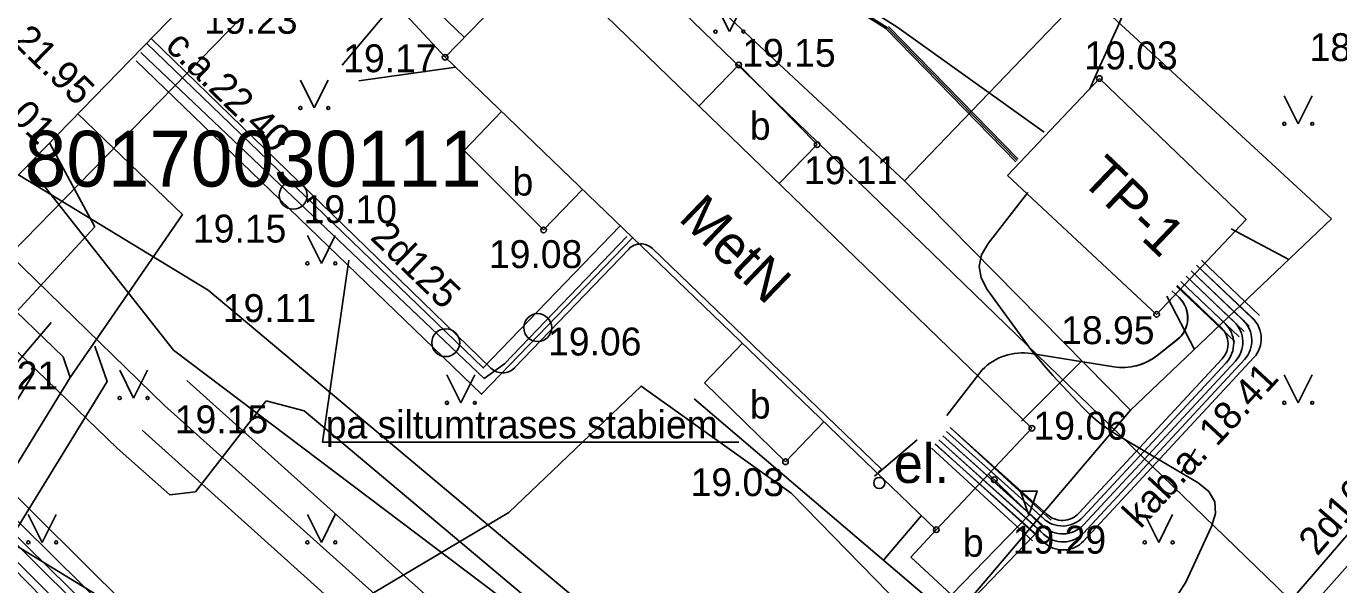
# Model space of a CAD drawing. Extents: x 532933 to 533143, y 328014 to 328163.
# Drawn here: x 533002.21 to 533025.73, y 328041.74 to 328051.75 of the extents above; entities that cross this region are included whole.
import ezdxf

# ---------------------------------------------------------------- set-up
doc = ezdxf.new("R2010")
doc.units = 0
for name, color, linetype in [('BUVE_BDET_####_####_#', 7, 'Continuous'), ('BUVE_BDET_####_TKST_#', 7, 'Continuous'), ('BUVE_EKAS_####_####_#', 7, 'Continuous'), ('BUVE_EKAS_BPAL_####_#', 7, 'Continuous'), ('BUVE_EKAS_RAKS_TKST_#', 7, 'Continuous'), ('BUVE_ELEM_####_####_#', 7, 'Continuous'), ('CELI_CMAL_####_####_#', 7, 'Continuous'), ('CKOM_ZEMJ_####_####_#', 7, 'Continuous'), ('ELEK_ACRL_####_####_#', 7, 'Continuous'), ('ELEK_ELEM_####_####_#', 7, 'Continuous'), ('ELEK_STTP_####_####_#', 7, 'Continuous'), ('ELEK_STTP_####_TKST_#', 7, 'Continuous'), ('ELEK_VADP_NEDR_####_#', 7, 'Continuous'), ('ELEK_VADP_VSPR_####_#', 7, 'Continuous'), ('ELEK_VADP_ZSPR_####_#', 7, 'Continuous'), ('ELEK_VADP_ZSPR_TKST_#', 7, 'Continuous'), ('GAZE_VADV_ASP1_####_#', 7, 'Continuous'), ('RELJ_AATZ_####_TKST_#', 7, 'Continuous'), ('RELJ_ELEM_####_####_#', 7, 'Continuous'), ('RELJ_HORZ_PAMT_####_#', 7, 'Continuous'), ('RELJ_NOGA_####_####_#', 7, 'Continuous'), ('ROBZ_UZMR_####_####_#', 7, 'Continuous'), ('ROBZ_UZMR_####_TKST_#', 7, 'Continuous'), ('SAKT_VADV_PKAB_####_#', 7, 'Continuous'), ('SILT_VADP_UDEN_####_#', 7, 'Continuous'), ('SILT_VADP_UDEN_TKAM_#', 7, 'Continuous'), ('SILT_VADP_UDEN_TKST_#', 7, 'Continuous'), ('SILT_VADV_UDEN_####_#', 7, 'Continuous'), ('SILT_VADV_UDEN_TKST_#', 7, 'Continuous'), ('TERT_ELEM_####_####_#', 7, 'Continuous')]:
    doc.layers.add(name, color=color, linetype=linetype)

msp = doc.modelspace()

# ---------------------------------------------------------------- linework, layer by layer
at = {"layer": 'BUVE_BDET_####_####_#'}
for p, q in [((533010.062, 328051.548), (533009.227, 328052.357)), ((533014.266, 328050.322), (533014.977, 328051.055)), ((533016.382, 328049.627), (533014.977, 328051.055)), ((533010.727, 328050.22), (533010.058, 328049.525)), ((533011.482, 328048.098), (533010.058, 328049.525)), ((533015.704, 328048.928), (533016.382, 328049.627)), ((533012.179, 328048.823), (533011.482, 328048.098)), ((533015.043, 328046.067), (533014.365, 328045.361)), ((533015.814, 328043.944), (533014.365, 328045.361)), ((533016.504, 328044.661), (533015.814, 328043.944)), ((533018.791, 328041.559), (533020.193, 328043.004)), ((533018.061, 328042.236), (533018.515, 328042.726))]:
    msp.add_line(p, q, dxfattribs=at)
msp.add_lwpolyline([(533019.453, 328043.722), (533020.419, 328042.785), (533019.027, 328041.34), (533018.061, 328042.236)], dxfattribs=at)
at = {"layer": 'BUVE_EKAS_####_####_#'}
msp.add_line((533000, 328046.956), (533007.034, 328054.184), dxfattribs=at)
at = {"layer": 'BUVE_EKAS_BPAL_####_#'}
for p, q in [((533009.717, 328051.192), (533018.515, 328042.726)), ((533018.515, 328042.726), (533020.228, 328044.544))]:
    msp.add_line(p, q, dxfattribs=at)
msp.add_lwpolyline([(533009.717, 328051.192), (533011.485, 328053.017), (533020.228, 328044.544)], dxfattribs=at)
at = {"layer": 'BUVE_ELEM_####_####_#'}
for centre in [(533006.996, 328048.72), (533011.376, 328046.349), (533009.728, 328046.078)]:
    msp.add_circle(centre, 0.25, dxfattribs=at)
at = {"layer": 'CELI_CMAL_####_####_#'}
for points in [[(532988.134, 328056.767), (532997.581, 328045.566), (533000.47, 328043.392), (533005, 328040.625), (533007.859, 328041.253), (533010.858, 328043.033), (533013.229, 328045.301), (533015.914, 328043.382), (533018.913, 328040.311), (533019.227, 328038.915), (533018.286, 328036.96), (533015.914, 328034.657), (533011.586, 328033.95), (533007.336, 328035.18), (533001.373, 328038.391), (532990.886, 328046.732), (532984.581, 328053.078)], [(533000, 328045.688), (533008.25, 328054.143)]]:
    msp.add_lwpolyline(points, dxfattribs=at)
at = {"layer": 'CKOM_ZEMJ_####_####_#'}
for p, q in [((533011.319, 328055.149), (533007.875, 328051.053)), ((533011.319, 328055.149), (533017.946, 328048.981)), ((533017.946, 328048.981), (533021.195, 328052.362)), ((533021.195, 328052.362), (533025.595, 328048.296)), ((533009.911, 328051.016), (533008.174, 328050.77)), ((533017.946, 328048.981), (533021.997, 328044.867)), ((533025.595, 328048.296), (533021.997, 328044.867)), ((533023.798, 328048.12), (533024.833, 328047.57)), ((533022.644, 328046.909), (533023.142, 328045.958)), ((533020.04, 328044.673), (533021.125, 328045.753)), ((533014.18, 328045.072), (533018.81, 328041.124)), ((533018.81, 328041.124), (533021.997, 328044.867)), ((533018.253, 328042.982), (533017.571, 328042.181))]:
    msp.add_line(p, q, dxfattribs=at)
at = {"layer": 'ELEK_ACRL_####_####_#'}
for p, q in [((533017.637, 328051.726), (533015.11, 328053.32)), ((533017.808, 328051.736), (533015.176, 328053.396)), ((533017.637, 328051.726), (533019.963, 328049.343)), ((533017.808, 328051.736), (533020.447, 328049.851)), ((533022.466, 328045.845), (533022.829, 328046.127)), ((533020.218, 328045.883), (533021.694, 328045.647)), ((533019.34, 328045.591), (533018.702, 328044.774)), ((533020.574, 328042.898), (533018.765, 328044.558)), ((533017.411, 328043.688), (533018.174, 328044.337)), ((533018.564, 328044.336), (533020.393, 328042.696)), ((533018.63, 328044.41), (533020.46, 328042.77)), ((533018.697, 328044.484), (533020.442, 328042.921)), ((533020.239, 328042.526), (533018.427, 328044.19)), ((533018.497, 328044.261), (533020.326, 328042.621))]:
    msp.add_line(p, q, dxfattribs=at)
for points in [[(533024.22, 328046.479), (533023.179, 328047.47)], [(533024.304, 328046.567), (533023.264, 328047.559)], [(533023.939, 328046.184), (533022.898, 328047.175)], [(533024.031, 328046.281), (533022.991, 328047.272)], [(533024.122, 328046.376), (533023.081, 328047.367)], [(533022.738, 328047.007), (533022.864, 328046.887)], [(533023.861, 328046.102), (533022.821, 328047.094)]]:
    msp.add_lwpolyline(points, dxfattribs=at)
for centre, radius, start, end in [((533022.522, 328046.522), 0.5, 307.8534, 46.3786), ((533020.059, 328044.896), 1, 80.8914, 136.0178), ((533021.852, 328046.634), 1, 260.8914, 307.8534)]:
    msp.add_arc(centre, radius, start, end, dxfattribs=at)
at = {"layer": 'ELEK_ELEM_####_####_#'}
msp.add_circle((533017.494, 328043.565), 0.1, dxfattribs=at)
at = {"layer": 'ELEK_STTP_####_####_#'}
for p, q in [((533019.793, 328049.077), (533021.437, 328050.813)), ((533022.463, 328046.586), (533019.793, 328049.077))]:
    msp.add_line(p, q, dxfattribs=at)
msp.add_lwpolyline([(533021.437, 328050.813), (533024.065, 328048.285), (533022.463, 328046.586)], dxfattribs=at)
at = {"layer": 'ELEK_VADP_NEDR_####_#'}
for p, q in [((533000, 328044.195), (533020.885, 328023.4)), ((533000, 328044.054), (533020.527, 328023.205))]:
    msp.add_line(p, q, dxfattribs=at)
for points in [[(533000, 328045.345), (533021.675, 328023.83)], [(533000, 328044.918), (533021.444, 328023.704)], [(533000, 328044.62), (533018.606, 328026.308)], [(533000, 328044.488), (533021.116, 328023.525)]]:
    msp.add_lwpolyline(points, dxfattribs=at)
at = {"layer": 'ELEK_VADP_VSPR_####_#'}
msp.add_lwpolyline([(533020.447, 328049.851), (533017.808, 328051.736), (533015.176, 328053.396), (533012.716, 328055.553), (533009.299, 328059.617), (533005.836, 328063.124)], dxfattribs=at)
at = {"layer": 'ELEK_VADP_ZSPR_####_#'}
for p, q in [((533015.1, 328053.29), (533017.621, 328051.701)), ((533010.538, 328045.622), (533004.45, 328051.529)), ((533013.007, 328047.756), (533010.963, 328045.629)), ((533022.738, 328047.007), (533022.864, 328046.887)), ((533020.495, 328043.007), (533018.764, 328044.559)), ((533020.436, 328042.647), (533018.562, 328044.337)), ((533020.432, 328042.79), (533018.63, 328044.411)), ((533018.697, 328044.484), (533020.428, 328042.933)), ((533020.428, 328042.933), (533018.697, 328044.484)), ((533020.44, 328042.505), (533018.494, 328044.263))]:
    msp.add_line(p, q, dxfattribs=at)
for points in [[(533017.615, 328051.705), (533019.942, 328049.322)], [(533017.658, 328051.747), (533019.985, 328049.364)], [(533017.533, 328043.814), (533013.432, 328047.764)], [(533023.179, 328047.47), (533024.183, 328046.514)], [(533022.898, 328047.175), (533023.688, 328046.422)], [(533022.991, 328047.272), (533023.852, 328046.452)], [(533023.081, 328047.367), (533024.013, 328046.479)], [(533022.829, 328047.103), (533023.619, 328046.35)], [(533022.83, 328046.133), (533022.474, 328045.851)], [(533021.694, 328045.647), (533020.218, 328045.883)], [(533023.636, 328045.788), (533021.068, 328043.021)], [(533023.873, 328045.75), (533021.146, 328042.81)], [(533024.035, 328045.777), (533021.15, 328042.667)], [(533024.204, 328045.812), (533021.154, 328042.524)], [(533019.34, 328045.591), (533018.702, 328044.774)], [(533023.71, 328045.72), (533021.142, 328042.953)], [(533017.411, 328043.688), (533018.174, 328044.337)], [(533017.533, 328043.814), (533017.482, 328043.761)]]:
    msp.add_lwpolyline(points, dxfattribs=at)
for centre, radius, start, end in [((533013.223, 328047.548), 0.3, 46.0779, 136.1332), ((533022.519, 328046.525), 0.5, 308.4459, 46.3786), ((533023.507, 328046.09), 0.5, 317.1451, 46.3786), ((533023.668, 328046.117), 0.5, 317.1451, 46.3786), ((533023.838, 328046.152), 0.5, 317.1451, 46.3786), ((533023.343, 328046.06), 0.4, 317.1451, 46.3786), ((533023.343, 328046.06), 0.5, 317.1451, 46.3786), ((533020.059, 328044.896), 1, 80.8914, 136.0178), ((533021.852, 328046.634), 1, 260.8914, 308.4459), ((533010.747, 328045.837), 0.3, 225.8619, 316.1332), ((533020.775, 328043.293), 0.5, 226.0387, 317.1451), ((533020.775, 328043.293), 0.4, 226.0387, 317.1451), ((533020.779, 328043.15), 0.5, 226.0387, 317.1451), ((533020.783, 328043.007), 0.5, 226.0387, 317.1451), ((533020.787, 328042.864), 0.5, 226.0387, 317.1451)]:
    msp.add_arc(centre, radius, start, end, dxfattribs=at)
at = {"layer": 'ELEK_VADP_ZSPR_TKST_#'}
for p, q in [((533007.991, 328047.556), (533007.52, 328044.295)), ((533010.963, 328045.629), (533010.963, 328045.629)), ((533007.52, 328044.295), (533014.976, 328044.295))]:
    msp.add_line(p, q, dxfattribs=at)
at = {"layer": 'GAZE_VADV_ASP1_####_#'}
msp.add_line((533007.418, 328053.682), (533009.717, 328051.192), dxfattribs=at)
at = {"layer": 'RELJ_ELEM_####_####_#'}
msp.add_lwpolyline([(533020.024, 328043.418), (533020.324, 328043.418), (533020.174, 328042.985)], close=True, dxfattribs=at)
for centre in [(533009.717, 328051.192), (533014.977, 328051.055), (533021.437, 328050.813), (533016.382, 328049.627), (533011.482, 328048.098), (533022.463, 328046.586), (533020.228, 328044.544), (533015.814, 328043.944), (533019.555, 328043.623), (533018.515, 328042.726)]:
    msp.add_circle(centre, 0.05, dxfattribs=at)
at = {"layer": 'RELJ_HORZ_PAMT_####_#'}
msp.add_line((533023.159, 328044.175), (533022.903, 328043.745), dxfattribs=at)
for points in [[(533021.866, 328051.966), (533021.76, 328051.733), (533021.655, 328051.5), (533021.55, 328051.266), (533021.447, 328051.033), (533021.267, 328050.626)], [(533020.156, 328048.77), (533019.444, 328047.856), (533019.324, 328047.652), (533019.282, 328047.446), (533019.317, 328047.238), (533019.43, 328047.03), (533020.113, 328046.089), (533020.229, 328045.933), (533020.35, 328045.782), (533020.476, 328045.634), (533020.606, 328045.491), (533021.136, 328044.923), (533021.272, 328044.787), (533021.418, 328044.661), (533021.572, 328044.546), (533021.734, 328044.441), (533023.207, 328043.564), (533023.399, 328043.41), (533023.504, 328043.229), (533023.52, 328043.02), (533023.448, 328042.784), (533022.986, 328041.787), (533022.85, 328041.572)]]:
    msp.add_lwpolyline(points, dxfattribs=at)
at = {"layer": 'RELJ_NOGA_####_####_#'}
msp.add_spline([(533036.778, 328051.985), (533034.856, 328064.958), (533028.737, 328060.034), (533025.855, 328056.237), (533030.353, 328047.862), (533030.341, 328043.495), (533028.835, 328039.173), (533026.009, 328035.465), (533024.217, 328033.207)], degree=3, dxfattribs=at)
at = {"layer": 'ROBZ_UZMR_####_####_#'}
for points in [[(532993.949, 328071.405), (532999.253, 328076.841), (533001.874, 328079.871), (533025.763, 328107.492), (533029.138, 328104.514), (533014.917, 328088.072), (533037.903, 328068.645), (533030.421, 328036.082)], [(532979.271, 328056.364), (532993.949, 328071.405), (533030.421, 328036.082), (533029.157, 328030.58), (533020.389, 328026.352), (532998.604, 328038.086)]]:
    msp.add_lwpolyline(points, close=True, dxfattribs=at)
at = {"layer": 'SAKT_VADV_PKAB_####_#'}
msp.add_lwpolyline([(533004.265, 328051.279), (533010.415, 328045.437), (533010.783, 328045.7), (533012.973, 328047.981)], dxfattribs=at)
at = {"layer": 'SILT_VADP_UDEN_####_#'}
for p, q in [((533005.014, 328048.373), (533003.003, 328045.454)), ((533003.444, 328048.152), (533002.038, 328046.631)), ((533005.244, 328043.403), (533006.51, 328045.039)), ((533006.51, 328045.039), (533007.19, 328044.859)), ((533007.19, 328044.859), (533019.249, 328034.732)), ((533003.843, 328044.186), (533004.789, 328043.349)), ((533004.789, 328043.349), (533005.244, 328043.403))]:
    msp.add_line(p, q, dxfattribs=at)
for points in [[(533004.853, 328045.947), (533019.384, 328034.966), (533019.749, 328035.185), (533031.003, 328047.839), (533031.356, 328048.225), (533031.335, 328048.654), (533025.793, 328053.779), (533025.755, 328054.215), (533035.838, 328064.377), (533036.105, 328064.808), (533033.176, 328075.216), (533032.836, 328076.021), (533015.446, 328091.145), (533015.462, 328091.585), (533029.065, 328106.172), (533029.033, 328106.692), (533017.302, 328118.3), (533000, 328134.38)], [(533000, 328133.784), (533016.764, 328118.182), (533028.476, 328106.559), (533028.508, 328106.039), (533014.85, 328091.596), (533014.892, 328091.077), (533032.527, 328075.724), (533032.689, 328075.239), (533035.542, 328065.283), (533035.311, 328064.711), (533024.98, 328054.226), (533025.028, 328053.821), (533027.938, 328051.227), (533030.653, 328048.689), (533030.642, 328048.162), (533019.754, 328035.526), (533019.215, 328035.483), (533005.473, 328047.022)], [(533012.853, 328048.174), (533010.399, 328045.627), (533004.369, 328051.445)], [(533004.181, 328051.128), (533010.372, 328045.155), (533013.075, 328047.96)], [(533002.877, 328045.822), (533003.003, 328045.454), (533000, 328040.564)], [(533004.689, 328044.955), (533025.41, 328026.355)]]:
    msp.add_lwpolyline(points, dxfattribs=at)
at = {"layer": 'SILT_VADP_UDEN_TKAM_#'}
for p, q in [((533002.663, 328046.44), (533000.183, 328043.528)), ((533005.09, 328045.401), (533025.888, 328026.732)), ((533004.288, 328044.508), (533024.932, 328025.978))]:
    msp.add_line(p, q, dxfattribs=at)
for points in [[(533003.445, 328046.015), (533003.662, 328045.38), (533000, 328039.417)], [(533002.309, 328045.628), (533002.344, 328045.527), (533000, 328041.711)]]:
    msp.add_lwpolyline(points, dxfattribs=at)
at = {"layer": 'SILT_VADV_UDEN_####_#'}
for p, q in [((533003.135, 328050.187), (533005.014, 328048.373)), ((533002.632, 328049.66), (533003.444, 328048.152)), ((533004.853, 328045.947), (533002.24, 328049.26)), ((533002.074, 328049.088), (533005.473, 328047.022)), ((533001.281, 328048.272), (533004.689, 328044.955)), ((533000.829, 328047.798), (533002.877, 328045.822)), ((533000.478, 328047.434), (533003.843, 328044.186))]:
    msp.add_line(p, q, dxfattribs=at)
at = {"layer": 'TERT_ELEM_####_####_#'}
for p, q in [((533014.561, 328052.153), (533014.811, 328051.653)), ((533014.811, 328051.653), (533015.061, 328052.153)), ((533007.124, 328050.784), (533007.374, 328050.284)), ((533007.374, 328050.284), (533007.624, 328050.784)), ((533024.75, 328050.5), (533025, 328050)), ((533025, 328050), (533025.25, 328050.5)), ((533007.25, 328048), (533007.5, 328047.5)), ((533007.5, 328047.5), (533007.75, 328048)), ((533003.888, 328045.586), (533004.138, 328045.086)), ((533004.138, 328045.086), (533004.388, 328045.586)), ((533009.75, 328045.5), (533010, 328045)), ((533010, 328045), (533010.25, 328045.5)), ((533024.75, 328045.5), (533025, 328045)), ((533025, 328045), (533025.25, 328045.5)), ((533002.25, 328043), (533002.5, 328042.5)), ((533002.5, 328042.5), (533002.75, 328043)), ((533007.25, 328043), (533007.5, 328042.5)), ((533007.5, 328042.5), (533007.75, 328043)), ((533022.25, 328043), (533022.5, 328042.5)), ((533022.5, 328042.5), (533022.75, 328043))]:
    msp.add_line(p, q, dxfattribs=at)
for centre, radius in [((533014.561, 328051.653), 0.028), ((533015.061, 328051.653), 0.0263), ((533007.124, 328050.283), 0.028), ((533007.624, 328050.283), 0.0263), ((533024.75, 328050), 0.028), ((533025.25, 328050), 0.0263), ((533007.25, 328047.5), 0.028), ((533007.75, 328047.5), 0.0263), ((533003.888, 328045.086), 0.028), ((533004.388, 328045.086), 0.0263), ((533009.75, 328045), 0.028), ((533010.25, 328045), 0.0263), ((533024.75, 328045), 0.028), ((533025.25, 328045), 0.0263), ((533002.25, 328042.5), 0.028), ((533002.75, 328042.5), 0.0263), ((533007.25, 328042.5), 0.028), ((533007.75, 328042.5), 0.0263), ((533022.25, 328042.5), 0.028), ((533022.75, 328042.5), 0.0263)]:
    msp.add_circle(centre, radius, dxfattribs=at)

# ---------------------------------------------------------------- texts
at = {"layer": 'BUVE_BDET_####_TKST_#'}
for p in [(533014.99, 328049.714), (533010.739, 328048.715), (533014.99, 328044.719), (533018.807, 328042.244)]:
    msp.add_text(' b', height=0.5, dxfattribs=at).set_placement(p)
at = {"layer": 'BUVE_EKAS_RAKS_TKST_#'}
msp.add_text('MetN', height=0.7, rotation=316.0745, dxfattribs=at).set_placement((533013.877, 328048.286))
at = {"layer": 'ELEK_ELEM_####_####_#'}
msp.add_text(' el.', height=0.7, dxfattribs=at).set_placement((533017.494, 328043.565))
at = {"layer": 'ELEK_STTP_####_TKST_#'}
msp.add_text('TP-1', height=0.7, rotation=316.2208, dxfattribs=at).set_placement((533021.078, 328048.98))
at = {"layer": 'ELEK_VADP_ZSPR_TKST_#'}
msp.add_text('kab.a. 18.41', height=0.5, rotation=47.1451, dxfattribs=at).set_placement((533022.173, 328042.728))
msp.add_text('pa siltumtrases stabiem', height=0.5, dxfattribs=at).set_placement((533007.578, 328044.362))
at = {"layer": 'RELJ_AATZ_####_TKST_#'}
for s, p in [(' 19.23', (533005.215, 328051.614)), (' 18.85', (533025.017, 328051.124)), (' 19.17', (533007.706, 328050.925)), (' 19.15', (533014.854, 328051.022)), (' 19.03', (533020.981, 328050.976)), (' 19.11', (533015.96, 328048.919)), (' 19.10', (533006.996, 328048.22)), (' 19.15', (533005.014, 328047.873)), (' 19.08', (533010.316, 328047.415)), (' 19.11', (533005.55, 328046.448)), (' 18.95', (533020.566, 328046.052)), (' 19.06', (533011.376, 328045.849)), (' 19.21', (533000.929, 328045.241)), (' 19.15', (533004.689, 328044.455)), (' 19.06', (533020.071, 328044.341)), (' 19.03', (533013.929, 328043.329)), (' 19.29', (533019.7, 328042.298))]:
    msp.add_text(s, height=0.5, dxfattribs=at).set_placement(p)
at = {"layer": 'ROBZ_UZMR_####_TKST_#'}
msp.add_text('80170030111', height=1, dxfattribs=at).set_placement((533002.188, 328048.875))
at = {"layer": 'SILT_VADP_UDEN_TKST_#'}
for s, rotation, p in [('2d125', 315.8657, (533008.357, 328047.947)), ('2d168/280', 49.2497, (533025.34, 328042.239))]:
    msp.add_text(s, height=0.5, rotation=rotation, dxfattribs=at).set_placement(p)
at = {"layer": 'SILT_VADV_UDEN_TKST_#'}
for s, p in [('c.a.21.95', (533001.16, 328052.217)), ('c.a.22.01', (533000.462, 328051.514)), ('c.a.22.40', (533004.68, 328051.368))]:
    msp.add_text(s, height=0.5, rotation=315.8474, dxfattribs=at).set_placement(p)

doc.saveas('drawing.dxf')
